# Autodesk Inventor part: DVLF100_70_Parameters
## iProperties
Created: 2010-03
Part Number: DVLF100_70_Parameters
Document SubType Name: Modeling
Designer: TB
Density: 1 g/cm^3
Slaglengde: 100.000 mm
Vinkel_Plussport: 0.00 deg
Vinkel_Minusport: 0.00 deg
Forlengelse_rør: 0.000 mm
Author: TB
